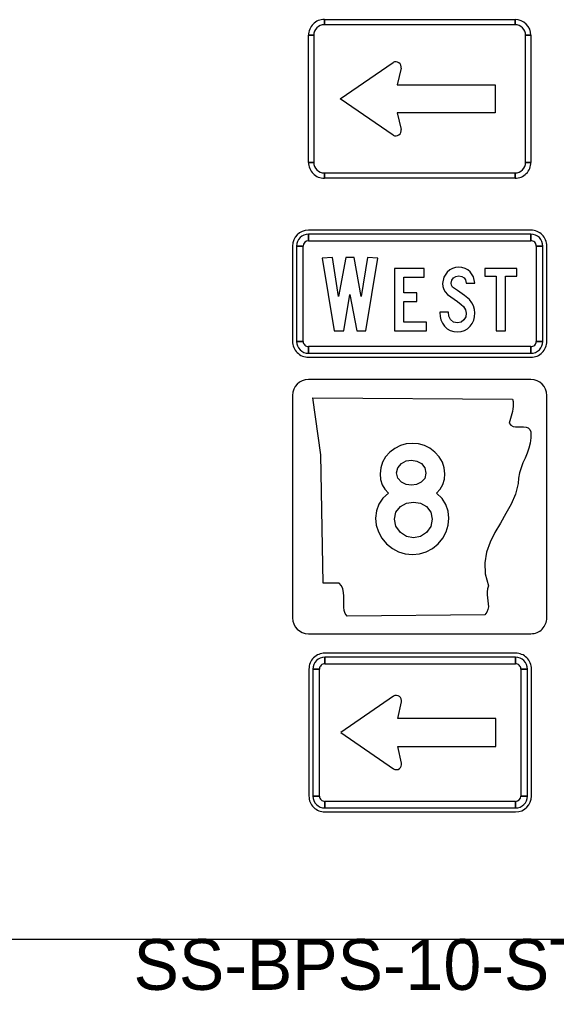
# Model space of a CAD drawing. Extents: x 1001568 to 1002149, y 1840825 to 1841423.
# Drawn here: x 1001894.06 to 1001898.28, y 1841295.06 to 1841302.71 of the extents above; entities that cross this region are included whole.
import ezdxf

# ---------------------------------------------------------------- set-up
doc = ezdxf.new("R2010")
doc.units = 0
for name, color, linetype in [('40', 7, 'Continuous'), ('R_No Plot', 7, 'Continuous'), ('SIGNS', 7, 'Continuous')]:
    doc.layers.add(name, color=color, linetype=linetype)

msp = doc.modelspace()

# ---------------------------------------------------------------- linework, layer by layer
at = {"layer": 'R_No Plot'}
msp.add_line((1001890.6501, 1841295.4691), (1001982.1327, 1841295.4691), dxfattribs=at)
at = {"layer": 'SIGNS'}
for p, q in [((1001896.4558, 1841302.7062), (1001896.4558, 1841302.6645)), ((1001897.9558, 1841302.6645), (1001897.9558, 1841302.7062)), ((1001896.3724, 1841302.5812), (1001896.3308, 1841302.5812)), ((1001898.0808, 1841302.5812), (1001898.0391, 1841302.5812)), ((1001896.5808, 1841302.0812), (1001896.996, 1841302.3664)), ((1001897.0589, 1841302.3219), (1001897.0287, 1841302.1906)), ((1001897.0287, 1841302.1906), (1001897.7995, 1841302.1906)), ((1001897.7995, 1841302.1906), (1001897.7995, 1841301.9718)), ((1001896.996, 1841301.796), (1001896.5808, 1841302.0812)), ((1001897.7995, 1841301.9718), (1001897.0287, 1841301.9718)), ((1001897.0287, 1841301.9718), (1001897.0589, 1841301.8405)), ((1001896.3308, 1841301.5812), (1001896.3724, 1841301.5812)), ((1001898.0391, 1841301.5812), (1001898.0808, 1841301.5812)), ((1001896.4558, 1841301.4979), (1001896.4558, 1841301.4562)), ((1001897.9558, 1841301.4562), (1001897.9558, 1841301.4979)), ((1001898.0808, 1841301.0476), (1001896.3308, 1841301.0476)), ((1001896.3308, 1841300.9643), (1001896.3308, 1841301.0164)), ((1001898.0808, 1841301.0164), (1001898.0808, 1841300.9643)), ((1001896.2058, 1841300.9226), (1001896.2058, 1841300.1726)), ((1001896.237, 1841300.9226), (1001896.2891, 1841300.9226)), ((1001898.1224, 1841300.9226), (1001898.1745, 1841300.9226)), ((1001898.2058, 1841300.1726), (1001898.2058, 1841300.9226)), ((1001896.2891, 1841300.1726), (1001896.237, 1841300.1726)), ((1001898.1745, 1841300.1726), (1001898.1224, 1841300.1726)), ((1001896.3308, 1841300.0789), (1001896.3308, 1841300.131)), ((1001898.0808, 1841300.131), (1001898.0808, 1841300.0789)), ((1001896.3308, 1841300.0476), (1001898.0808, 1841300.0476)), ((1001898.0808, 1841299.872), (1001896.3308, 1841299.872)), ((1001896.2058, 1841299.747), (1001896.2058, 1841297.997)), ((1001898.2058, 1841297.997), (1001898.2058, 1841299.747)), ((1001896.2058, 1841297.997), (1001896.2058, 1841297.997)), ((1001896.3308, 1841297.872), (1001898.0808, 1841297.872)), ((1001897.9597, 1841297.7191), (1001896.4597, 1841297.7191)), ((1001896.4597, 1841297.6358), (1001896.4597, 1841297.6879)), ((1001897.9597, 1841297.6879), (1001897.9597, 1841297.6358)), ((1001896.3347, 1841297.5941), (1001896.3347, 1841296.5941)), ((1001896.3659, 1841297.5941), (1001896.418, 1841297.5941)), ((1001898.0014, 1841297.5941), (1001898.0534, 1841297.5941)), ((1001898.0847, 1841296.5941), (1001898.0847, 1841297.5941)), ((1001896.9999, 1841297.3793), (1001896.5847, 1841297.0941)), ((1001897.0326, 1841297.2035), (1001897.0628, 1841297.3348)), ((1001897.8034, 1841297.2035), (1001897.0326, 1841297.2035)), ((1001897.8034, 1841297.2035), (1001897.8034, 1841297.2035)), ((1001897.8034, 1841296.9847), (1001897.8034, 1841297.2035)), ((1001896.5847, 1841297.0941), (1001896.5847, 1841297.0941)), ((1001896.5847, 1841297.0941), (1001896.9999, 1841296.8089)), ((1001897.0628, 1841296.8534), (1001897.0326, 1841296.9847)), ((1001897.0326, 1841296.9847), (1001897.8034, 1841296.9847)), ((1001896.418, 1841296.5941), (1001896.3659, 1841296.5941)), ((1001896.4597, 1841296.5004), (1001896.4597, 1841296.5524)), ((1001897.9597, 1841296.5524), (1001897.9597, 1841296.5004)), ((1001898.0534, 1841296.5941), (1001898.0014, 1841296.5941)), ((1001896.4597, 1841296.4691), (1001897.9597, 1841296.4691))]:
    msp.add_line(p, q, dxfattribs=at)
for points in [[(1001896.4558, 1841302.7062), (1001897.9558, 1841302.7062), (1001897.9558, 1841302.6645), (1001896.4558, 1841302.6645), (1001896.4558, 1841302.7062), (1001896.4558, 1841302.7062)], [(1001896.3308, 1841301.5812), (1001896.3308, 1841302.5812), (1001896.3724, 1841302.5812), (1001896.3724, 1841301.5812), (1001896.3308, 1841301.5812), (1001896.3308, 1841301.5812)], [(1001898.0808, 1841302.5812), (1001898.0808, 1841301.5812), (1001898.0391, 1841301.5812), (1001898.0391, 1841302.5812), (1001898.0808, 1841302.5812), (1001898.0808, 1841302.5812)], [(1001897.9558, 1841301.4562), (1001896.4558, 1841301.4562), (1001896.4558, 1841301.4979), (1001897.9558, 1841301.4979), (1001897.9558, 1841301.4562), (1001897.9558, 1841301.4562)], [(1001898.0808, 1841301.0164), (1001896.3308, 1841301.0164), (1001896.3308, 1841300.9643), (1001898.0808, 1841300.9643), (1001898.0808, 1841301.0164), (1001898.0808, 1841301.0164)], [(1001896.237, 1841300.9226), (1001896.237, 1841300.1726), (1001896.2891, 1841300.1726), (1001896.2891, 1841300.9226), (1001896.237, 1841300.9226), (1001896.237, 1841300.9226)], [(1001898.1745, 1841300.1726), (1001898.1745, 1841300.9226), (1001898.1224, 1841300.9226), (1001898.1224, 1841300.1726), (1001898.1745, 1841300.1726), (1001898.1745, 1841300.1726)], [(1001896.533, 1841300.256), (1001896.6094, 1841300.256), (1001896.6564, 1841300.5411), (1001896.7125, 1841300.256), (1001896.7831, 1841300.256), (1001896.8762, 1841300.828), (1001896.7956, 1841300.8327), (1001896.7448, 1841300.5253), (1001896.6894, 1841300.8327), (1001896.6248, 1841300.8327), (1001896.5677, 1841300.5253), (1001896.5192, 1841300.8327), (1001896.4378, 1841300.828)], [(1001897.3634, 1841300.4033), (1001897.3634, 1841300.3988), (1001897.3655, 1841300.3689), (1001897.3726, 1841300.3413), (1001897.3846, 1841300.3159), (1001897.4014, 1841300.2928), (1001897.4226, 1841300.2723), (1001897.4466, 1841300.2579), (1001897.473, 1841300.2493), (1001897.5023, 1841300.2464), (1001897.5315, 1841300.2491), (1001897.5581, 1841300.2576), (1001897.5817, 1841300.2716), (1001897.6027, 1841300.2914), (1001897.6191, 1841300.3141), (1001897.6308, 1841300.3392), (1001897.6379, 1841300.3664), (1001897.6403, 1841300.3961), (1001897.6374, 1841300.4245), (1001897.6292, 1841300.4515), (1001897.6154, 1841300.4771), (1001897.5963, 1841300.5013), (1001897.5593, 1841300.5331), (1001897.5023, 1841300.5722), (1001897.4647, 1841300.6004), (1001897.4566, 1841300.6147), (1001897.4538, 1841300.6311), (1001897.4582, 1841300.653), (1001897.4714, 1841300.6715), (1001897.4905, 1841300.6839), (1001897.5132, 1841300.6882), (1001897.5375, 1841300.6841), (1001897.5553, 1841300.6724), (1001897.5648, 1841300.6557), (1001897.5721, 1841300.6312), (1001897.6403, 1841300.6312), (1001897.6292, 1841300.6813), (1001897.6032, 1841300.7206), (1001897.5841, 1841300.7359), (1001897.5626, 1841300.7471), (1001897.5381, 1841300.7537), (1001897.5113, 1841300.756), (1001897.4863, 1841300.7535), (1001897.4633, 1841300.7464), (1001897.442, 1841300.7346), (1001897.4228, 1841300.7181), (1001897.3948, 1841300.6769), (1001897.3856, 1841300.6291), (1001897.3879, 1841300.6045), (1001897.3949, 1841300.582), (1001897.4066, 1841300.5611), (1001897.4232, 1841300.5422), (1001897.5028, 1841300.4852), (1001897.5324, 1841300.4627), (1001897.5507, 1841300.446), (1001897.567, 1841300.4215), (1001897.5725, 1841300.3954), (1001897.5677, 1841300.3664), (1001897.5537, 1841300.3417), (1001897.5306, 1841300.3237), (1001897.5023, 1841300.3177), (1001897.4722, 1841300.3243), (1001897.4489, 1841300.3444), (1001897.4352, 1841300.3712), (1001897.4312, 1841300.4033)], [(1001897.2602, 1841300.3232), (1001897.0797, 1841300.3232), (1001897.0797, 1841300.4867), (1001897.1821, 1841300.4867), (1001897.1821, 1841300.554), (1001897.0797, 1841300.554), (1001897.0797, 1841300.679), (1001897.2415, 1841300.679), (1001897.2415, 1841300.7463), (1001897.008, 1841300.7463), (1001897.008, 1841300.256), (1001897.2602, 1841300.256)], [(1001897.8083, 1841300.256), (1001897.8794, 1841300.256), (1001897.8794, 1841300.6847), (1001897.9709, 1841300.6847), (1001897.9709, 1841300.7463), (1001897.7187, 1841300.7463), (1001897.7187, 1841300.6847), (1001897.8083, 1841300.6847)], [(1001896.3308, 1841300.0789), (1001898.0808, 1841300.0789), (1001898.0808, 1841300.131), (1001896.3308, 1841300.131), (1001896.3308, 1841300.0789), (1001896.3308, 1841300.0789)], [(1001897.9357, 1841299.7176), (1001897.9404, 1841299.6985), (1001897.942, 1841299.6791), (1001897.9414, 1841299.66), (1001897.939, 1841299.6409), (1001897.935, 1841299.6218), (1001897.9303, 1841299.6031), (1001897.9246, 1841299.584), (1001897.919, 1841299.5656), (1001897.9136, 1841299.5473), (1001897.9086, 1841299.5289), (1001897.9226, 1841299.5128), (1001897.94, 1841299.5036), (1001897.9597, 1841299.4995), (1001897.9811, 1841299.4992), (1001898.0025, 1841299.4999), (1001898.0233, 1841299.5003), (1001898.0423, 1841299.4981), (1001898.059, 1841299.4918), (1001898.072, 1841299.4797), (1001898.08, 1841299.4595), (1001898.0807, 1841299.414), (1001898.075, 1841299.3714), (1001898.0644, 1841299.331), (1001898.05, 1841299.2925), (1001898.0343, 1841299.2543), (1001898.0182, 1841299.2165), (1001898.0032, 1841299.1779), (1001897.9912, 1841299.1383), (1001897.9828, 1841299.0968), (1001897.9808, 1841299.0528), (1001897.9587, 1841298.9705), (1001897.925, 1841298.8923), (1001897.8842, 1841298.8167), (1001897.8401, 1841298.7418), (1001897.797, 1841298.6673), (1001897.7592, 1841298.5913), (1001897.7312, 1841298.5127), (1001897.7168, 1841298.4301), (1001897.7201, 1841298.3428), (1001897.7459, 1841298.2492), (1001897.7382, 1841298.226), (1001897.7355, 1841298.2022), (1001897.7362, 1841298.1783), (1001897.7392, 1841298.1541), (1001897.7425, 1841298.1302), (1001897.7452, 1841298.1067), (1001897.7459, 1841298.0836), (1001897.7425, 1841298.0619), (1001897.7342, 1841298.0406), (1001897.7188, 1841298.0208), (1001896.6351, 1841298.0109), (1001896.6204, 1841298.0307), (1001896.612, 1841298.0546), (1001896.6084, 1841298.081), (1001896.608, 1841298.1093), (1001896.6087, 1841298.139), (1001896.609, 1841298.1684), (1001896.607, 1841298.1974), (1001896.6013, 1841298.2242), (1001896.5903, 1841298.2484), (1001896.5719, 1841298.269), (1001896.4456, 1841298.269), (1001896.4276, 1841299.2807), (1001896.3641, 1841299.7275), (1001897.9357, 1841299.7176), (1001897.9357, 1841299.7176)], [(1001897.9597, 1841297.6879), (1001896.4597, 1841297.6879), (1001896.4597, 1841297.6358), (1001897.9597, 1841297.6358), (1001897.9597, 1841297.6879), (1001897.9597, 1841297.6879)], [(1001896.3659, 1841297.5941), (1001896.3659, 1841296.5941), (1001896.418, 1841296.5941), (1001896.418, 1841297.5941), (1001896.3659, 1841297.5941), (1001896.3659, 1841297.5941)], [(1001898.0534, 1841296.5941), (1001898.0534, 1841297.5941), (1001898.0014, 1841297.5941), (1001898.0014, 1841296.5941), (1001898.0534, 1841296.5941), (1001898.0534, 1841296.5941)], [(1001896.4597, 1841296.5004), (1001897.9597, 1841296.5004), (1001897.9597, 1841296.5524), (1001896.4597, 1841296.5524), (1001896.4597, 1841296.5004), (1001896.4597, 1841296.5004)]]:
    msp.add_lwpolyline(points, close=True, dxfattribs=at)
for points in [[(1001896.3308, 1841299.872), (1001896.3308, 1841299.872)], [(1001898.0808, 1841299.872), (1001898.0808, 1841299.872)], [(1001896.2058, 1841299.747), (1001896.2058, 1841299.747)], [(1001897.3387, 1841298.9773), (1001897.3671, 1841299.0106), (1001897.3874, 1841299.0472), (1001897.3998, 1841299.0872), (1001897.404, 1841299.1305), (1001897.3988, 1841299.1783), (1001897.3841, 1841299.2228), (1001897.3593, 1841299.2639), (1001897.3251, 1841299.3013), (1001897.2853, 1841299.3311), (1001897.243, 1841299.3526), (1001897.1972, 1841299.3655), (1001897.1483, 1841299.3699), (1001897.0996, 1841299.3652), (1001897.0539, 1841299.3521), (1001897.0112, 1841299.3301), (1001896.9715, 1841299.2995), (1001896.9376, 1841299.2626), (1001896.9136, 1841299.2221), (1001896.8993, 1841299.1779), (1001896.8946, 1841299.1305), (1001896.8984, 1841299.0851), (1001896.9106, 1841299.0447), (1001896.9307, 1841299.0085), (1001896.9591, 1841298.9773), (1001896.9152, 1841298.9374), (1001896.884, 1841298.8914), (1001896.8652, 1841298.8396), (1001896.859, 1841298.7818), (1001896.8642, 1841298.7256), (1001896.8804, 1841298.6734), (1001896.9074, 1841298.625), (1001896.9454, 1841298.5804), (1001896.9905, 1841298.5427), (1001897.0393, 1841298.5162), (1001897.0919, 1841298.5003), (1001897.1483, 1841298.4951), (1001897.2044, 1841298.5003), (1001897.257, 1841298.5162), (1001897.3054, 1841298.5427), (1001897.3503, 1841298.5804), (1001897.3877, 1841298.625), (1001897.4146, 1841298.6734), (1001897.4308, 1841298.7256), (1001897.4361, 1841298.7818), (1001897.43, 1841298.8372), (1001897.4117, 1841298.8886), (1001897.3812, 1841298.9353), (1001897.3387, 1841298.9773)], [(1001897.2551, 1841299.1344), (1001897.2456, 1841299.0946), (1001897.217, 1841299.0634), (1001897.1811, 1841299.0456), (1001897.1411, 1841299.0397), (1001897.0996, 1841299.0456), (1001897.063, 1841299.0643), (1001897.0336, 1841299.0962), (1001897.0241, 1841299.137), (1001897.0336, 1841299.1783), (1001897.063, 1841299.2115), (1001897.0996, 1841299.2311), (1001897.1411, 1841299.2378), (1001897.1829, 1841299.2309), (1001897.2193, 1841299.2107), (1001897.2461, 1841299.1767), (1001897.2551, 1841299.1344)], [(1001897.3046, 1841298.7735), (1001897.2933, 1841298.7165), (1001897.2595, 1841298.6694), (1001897.2111, 1841298.6376), (1001897.1566, 1841298.627), (1001897.1024, 1841298.6376), (1001897.0548, 1841298.6696), (1001897.0191, 1841298.717), (1001897.0075, 1841298.7735), (1001897.0191, 1841298.8282), (1001897.0548, 1841298.8721), (1001897.1012, 1841298.8986), (1001897.1566, 1841298.9076), (1001897.2115, 1841298.8986), (1001897.2582, 1841298.8721), (1001897.293, 1841298.8282), (1001897.3046, 1841298.7735)], [(1001896.3308, 1841297.872), (1001896.3308, 1841297.872)], [(1001898.0808, 1841297.872), (1001898.0808, 1841297.872)]]:
    msp.add_lwpolyline(points, dxfattribs=at)
for centre, radius, start, end in [((1001896.4558, 1841302.5812), 0.125, 89.99979, 180), ((1001896.4558, 1841302.5812), 0.0833, 89.99979, 180), ((1001897.9558, 1841302.5812), 0.125, 0.00015, 89.99979), ((1001897.9558, 1841302.5812), 0.0833, 0.00015, 89.99979), ((1001897.0183, 1841302.3312), 0.0417, 347.04959, 122.27565), ((1001897.0183, 1841301.8312), 0.0417, 237.72408, 12.95014), ((1001896.4558, 1841301.5812), 0.125, 179.99973, 269.99994), ((1001896.4558, 1841301.5812), 0.0833, 179.99973, 269.99994), ((1001897.9558, 1841301.5812), 0.125, 269.99994, 0.00015), ((1001897.9558, 1841301.5812), 0.0833, 269.99994, 0.00015), ((1001896.3308, 1841300.9226), 0.125, 90.00021, 179.99985), ((1001896.3308, 1841300.9226), 0.0937, 90.00021, 179.99985), ((1001898.0808, 1841300.9226), 0.125, 0, 90.00021), ((1001898.0808, 1841300.9226), 0.0937, 0, 90.00021), ((1001896.3308, 1841300.9226), 0.0417, 90.00021, 179.99985), ((1001898.0808, 1841300.9226), 0.0417, 0, 90.00021), ((1001896.3308, 1841300.1726), 0.125, 179.99985, 270.00006), ((1001896.3308, 1841300.1726), 0.0937, 179.99985, 270.00006), ((1001896.3308, 1841300.1726), 0.0417, 179.99985, 270.00006), ((1001898.0808, 1841300.1726), 0.125, 270.00006, 0.00027), ((1001898.0808, 1841300.1726), 0.0937, 270.00006, 0.00027), ((1001898.0808, 1841300.1726), 0.0417, 270.00006, 0.00027), ((1001896.3308, 1841299.747), 0.125, 90.00021, 179.99985), ((1001898.0808, 1841299.747), 0.125, 360, 90), ((1001896.3308, 1841297.997), 0.125, 180, 270), ((1001898.0808, 1841297.997), 0.125, 270.00006, 0.00027), ((1001896.4597, 1841297.5941), 0.125, 90.00006, 180.00027), ((1001897.9597, 1841297.5941), 0.125, 359.99985, 90.00006), ((1001896.4597, 1841297.5941), 0.0937, 90.00006, 180.00027), ((1001896.4597, 1841297.5941), 0.0417, 90.00006, 180.00027), ((1001897.9597, 1841297.5941), 0.0937, 359.99985, 90.00006), ((1001897.9597, 1841297.5941), 0.0417, 359.99985, 90.00006), ((1001897.0222, 1841297.3441), 0.0417, 347.04986, 122.27592), ((1001897.0222, 1841296.8441), 0.0417, 237.72435, 12.95041), ((1001896.4597, 1841296.5941), 0.125, 180, 270.00021), ((1001896.4597, 1841296.5941), 0.0937, 180, 270.00021), ((1001896.4597, 1841296.5941), 0.0417, 180, 270.00021), ((1001897.9597, 1841296.5941), 0.0937, 270.00021, 359.99985), ((1001897.9597, 1841296.5941), 0.0417, 270.00021, 359.99985), ((1001897.9597, 1841296.5941), 0.125, 270.00021, 359.99985)]:
    msp.add_arc(centre, radius, start, end, dxfattribs=at)

# ---------------------------------------------------------------- texts
at = {"layer": '40'}
msp.add_text('SS-BPS-10-STA102+00NB', height=0.4, rotation=0, dxfattribs=at).set_placement((1001894.9548, 1841295.0691))

doc.saveas('drawing.dxf')
